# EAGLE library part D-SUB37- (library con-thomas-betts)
D-Subminiatur Connector Source: Electronioc Interconnects European Edition 1998
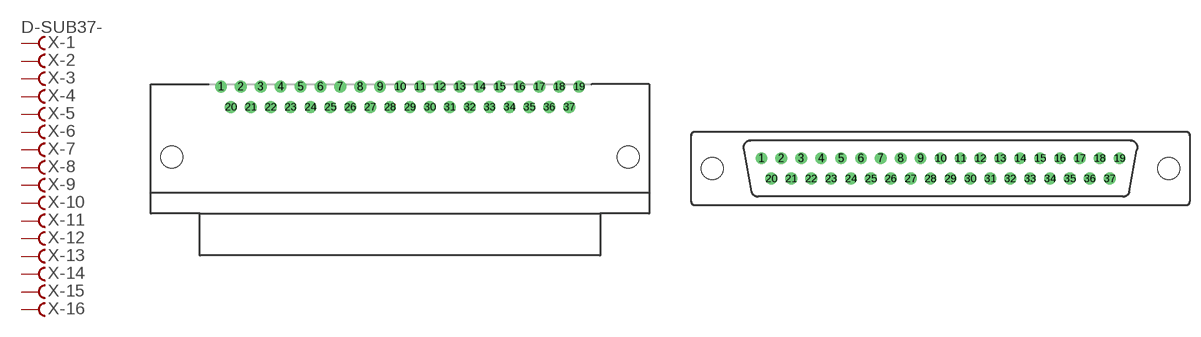
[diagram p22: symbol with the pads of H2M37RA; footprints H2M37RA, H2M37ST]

Designator prefix X; gates -1=FV -2=F -3=F -4=F -5=F -6=F -7=F -8=F -9=F -10=F -11=F -12=F -13=F -14=F -15=F -16=F -17=F -18=F -19=F -20=F -21=F -22=F -23=F -24=F -25=F -26=F -27=F -28=F -29=F -30=F -31=F -32=F -33=F -34=F -35=F -36=F -37=F

## D-SUB37-H2M37RA (OC_FARNELL: unknown; OC_NEWARK: unknown)  [H2M37RA]
1  -1:F  pas
2  -2:F  pas
3  -3:F  pas
4  -4:F  pas
5  -5:F  pas
6  -6:F  pas
7  -7:F  pas
8  -8:F  pas
9  -9:F  pas
10  -10:F  pas
11  -11:F  pas
12  -12:F  pas
13  -13:F  pas
14  -14:F  pas
15  -15:F  pas
16  -16:F  pas
17  -17:F  pas
18  -18:F  pas
19  -19:F  pas
20  -20:F  pas
21  -21:F  pas
22  -22:F  pas
23  -23:F  pas
24  -24:F  pas
25  -25:F  pas
26  -26:F  pas
27  -27:F  pas
28  -28:F  pas
29  -29:F  pas
30  -30:F  pas
31  -31:F  pas
32  -32:F  pas
33  -33:F  pas
34  -34:F  pas
35  -35:F  pas
36  -36:F  pas
37  -37:F  pas

## D-SUB37-H2M37ST (OC_FARNELL: unknown; OC_NEWARK: unknown)  [H2M37ST]
Pads as for H2M37RA

## D-SUB37-H2R37RA (OC_FARNELL: unknown; OC_NEWARK: unknown)  [H2R37RA]
Pads as for H2M37RA

## D-SUB37-H3R37ST (OC_FARNELL: unknown; OC_NEWARK: unknown)  [H2R37ST]
Pads as for H2M37RA

## D-SUB37-H3R37RA (OC_FARNELL: unknown; OC_NEWARK: unknown)  [H3R37RA]
Pads as for H2M37RA

## D-SUB37-H5M37RA (MPN: H5M37RA29CS; OC_FARNELL: unknown; OC_NEWARK: 93F8325)  [H5M37RA]
Pads as for H2M37RA

## D-SUB37-H5R37RA (OC_FARNELL: unknown; OC_NEWARK: unknown)  [H5R37RA]
Pads as for H2M37RA

## Footprint H2M37RA (pad centres in mm)
THOMAS&BETTS H2M37RA29A
drill 1.092 round: 1 -24.917,7.925; 2 -22.149,7.925; 3 -19.38,7.925; 4 -16.612,7.925; 5 -13.843,7.925; 6 -11.074,7.925; 7 -8.306,7.925; 8 -5.537,7.925; 9 -2.769,7.925; 10 0,7.925; 11 2.769,7.925; 12 5.537,7.925; 13 8.306,7.925; 14 11.074,7.925; 15 13.843,7.925; 16 16.612,7.925; 17 19.38,7.925; 18 22.149,7.925; 19 24.917,7.925; 20 -23.533,5.08; 21 -20.765,5.08; 22 -17.996,5.08; 23 -15.227,5.08; 24 -12.459,5.08; 25 -9.69,5.08; 26 -6.921,5.08; 27 -4.153,5.08; 28 -1.384,5.08; 29 1.384,5.08; 30 4.153,5.08; 31 6.921,5.08; 32 9.69,5.08; 33 12.459,5.08; 34 15.227,5.08; 35 17.996,5.08; 36 20.765,5.08; 37 23.533,5.08
hole 3.048 at -31.75,-1.905
hole 3.048 at 31.75,-1.905

## Footprint H2M37ST (pad centres in mm)
THOMAS&BETTS H2M37ST29x
drill 1.092 round: 1 -24.917,1.422; 2 -22.149,1.422; 3 -19.38,1.422; 4 -16.612,1.422; 5 -13.843,1.422; 6 -11.074,1.422; 7 -8.306,1.422; 8 -5.537,1.422; 9 -2.769,1.422; 10 0,1.422; 11 2.769,1.422; 12 5.537,1.422; 13 8.306,1.422; 14 11.074,1.422; 15 13.843,1.422; 16 16.612,1.422; 17 19.38,1.422; 18 22.149,1.422; 19 24.917,1.422; 20 -23.533,-1.422; 21 -20.765,-1.422; 22 -17.996,-1.422; 23 -15.227,-1.422; 24 -12.459,-1.422; 25 -9.69,-1.422; 26 -6.921,-1.422; 27 -4.153,-1.422; 28 -1.384,-1.422; 29 1.384,-1.422; 30 4.153,-1.422; 31 6.921,-1.422; 32 9.69,-1.422; 33 12.459,-1.422; 34 15.227,-1.422; 35 17.996,-1.422; 36 20.765,-1.422; 37 23.533,-1.422
hole 3.048 at -31.75,0
hole 3.048 at 31.75,0

## Footprint H2R37RA (pad centres in mm)
THOMAS&BETTS H2R37RA29A
drill 1.092 round: 1 24.917,7.925; 2 22.149,7.925; 3 19.38,7.925; 4 16.612,7.925; 5 13.843,7.925; 6 11.074,7.925; 7 8.306,7.925; 8 5.537,7.925; 9 2.769,7.925; 10 0,7.925; 11 -2.769,7.925; 12 -5.537,7.925; 13 -8.306,7.925; 14 -11.074,7.925; 15 -13.843,7.925; 16 -16.612,7.925; 17 -19.38,7.925; 18 -22.149,7.925; 19 -24.917,7.925; 20 23.533,5.08; 21 20.765,5.08; 22 17.996,5.08; 23 15.227,5.08; 24 12.459,5.08; 25 9.69,5.08; 26 6.921,5.08; 27 4.153,5.08; 28 1.384,5.08; 29 -1.384,5.08; 30 -4.153,5.08; 31 -6.921,5.08; 32 -9.69,5.08; 33 -12.459,5.08; 34 -15.227,5.08; 35 -17.996,5.08; 36 -20.765,5.08; 37 -23.533,5.08
hole 3.048 at -31.75,-1.905
hole 3.048 at 31.75,-1.905

## Footprint H2R37ST (pad centres in mm)
THOMAS&BETTS H2R37ST29x
drill 1.092 round: 1 24.917,1.422; 2 22.149,1.422; 3 19.38,1.422; 4 16.612,1.422; 5 13.843,1.422; 6 11.074,1.422; 7 8.306,1.422; 8 5.537,1.422; 9 2.769,1.422; 10 0,1.422; 11 -2.769,1.422; 12 -5.537,1.422; 13 -8.306,1.422; 14 -11.074,1.422; 15 -13.843,1.422; 16 -16.612,1.422; 17 -19.38,1.422; 18 -22.149,1.422; 19 -24.917,1.422; 20 23.533,-1.422; 21 20.765,-1.422; 22 17.996,-1.422; 23 15.227,-1.422; 24 12.459,-1.422; 25 9.69,-1.422; 26 6.921,-1.422; 27 4.153,-1.422; 28 1.384,-1.422; 29 -1.384,-1.422; 30 -4.153,-1.422; 31 -6.921,-1.422; 32 -9.69,-1.422; 33 -12.459,-1.422; 34 -15.227,-1.422; 35 -17.996,-1.422; 36 -20.765,-1.422; 37 -23.533,-1.422
hole 3.048 at -31.75,0
hole 3.048 at 31.75,0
